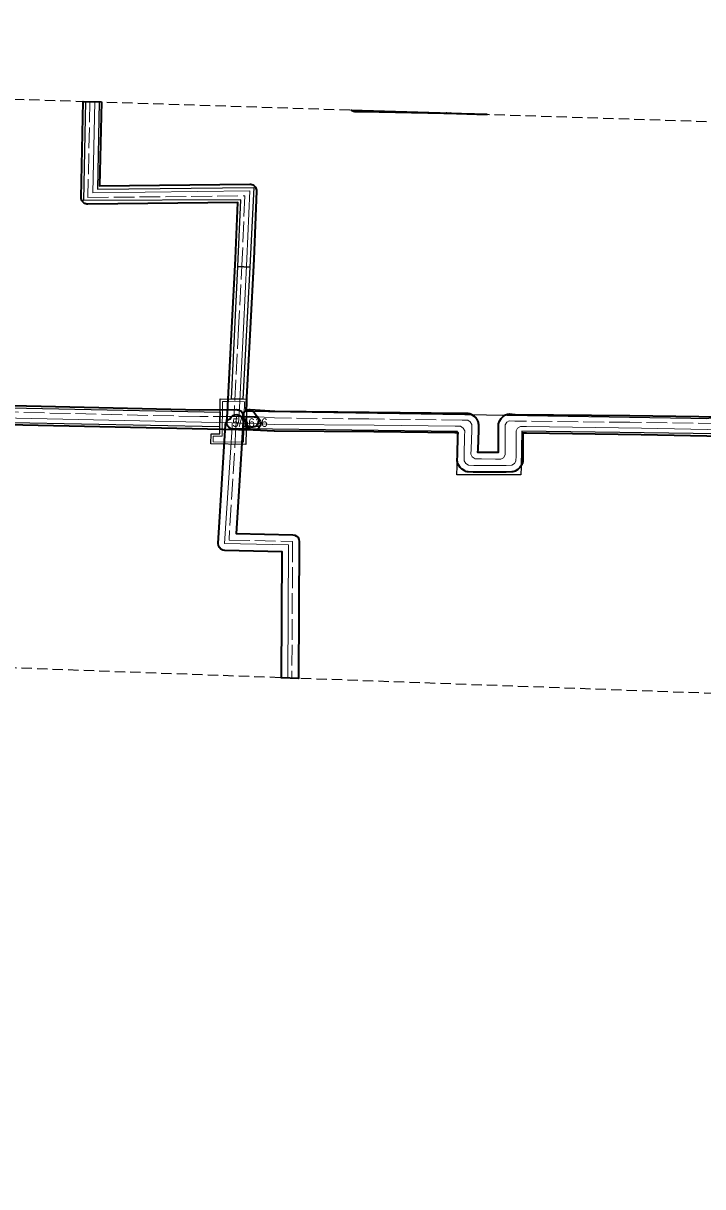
# Model space of a CAD drawing. Extents: x -451331 to -449998, y -1101254 to -1101132.
# Drawn here: x -451083.4 to -451012.5, y -1101253.5 to -1101132.1 of the extents above; entities that cross this region are included whole.
import ezdxf

# ---------------------------------------------------------------- set-up
doc = ezdxf.new("R2010")
doc.units = 0
doc.header["$LTSCALE"] = 0.36
doc.linetypes.add('LONG_DASHED', pattern=[7.5, 6, -1.5])
doc.linetypes.add('MEDIUM_DASHED', pattern=[4.5, 3, -1.5])
for name, color, linetype, lineweight in [('2', 7, 'Continuous', 13), ('3', 7, 'Continuous', 25), ('62', 7, 'MEDIUM_DASHED', 25), ('8', 7, 'Continuous', 35)]:
    doc.layers.add(name, color=color, linetype=linetype, lineweight=lineweight)

msp = doc.modelspace()

# ---------------------------------------------------------------- linework, layer by layer
at = {"layer": '2'}
for q in [(-451061.646, -1101174.239), (-451060.96, -1101173.819)]:
    msp.add_line((-451061.616, -1101173.805), q, dxfattribs=at)
at = {"layer": '2', "linetype": 'LONG_DASHED'}
for p, q in [((-451061.43, -1101172.861), (-451061.444, -1101173.121)), ((-451061.169, -1101173.119), (-451061.444, -1101173.121)), ((-451061.169, -1101173.119), (-451061.235, -1101174.261))]:
    msp.add_line(p, q, dxfattribs=at)
for points in [[(-451076.479, -1101140.271), (-451076.692, -1101150.286), (-451060.305, -1101150.097), (-451060.581, -1101156.665), (-451060.955, -1101163.903), (-451061.43, -1101172.861)], [(-451061.444, -1101173.121), (-451065.019, -1101173.141), (-451093.694, -1101172.465), (-451093.775, -1101176.839), (-451096.67, -1101176.755), (-451096.583, -1101172.448), (-451134.264, -1101171.549)], [(-451008.119, -1101173.899), (-451020.119, -1101173.739), (-451032.119, -1101173.609), (-451032.722, -1101173.571), (-451032.966, -1101173.719), (-451033.129, -1101173.986), (-451033.119, -1101174.579), (-451033.14, -1101176.469), (-451033.13, -1101177.147), (-451033.314, -1101177.432), (-451033.583, -1101177.57), (-451034.159, -1101177.57), (-451035.619, -1101177.55), (-451036.27, -1101177.539), (-451036.57, -1101177.359), (-451036.719, -1101177.075), (-451036.7, -1101176.559), (-451036.63, -1101174.55), (-451036.63, -1101173.975), (-451036.773, -1101173.677), (-451037.039, -1101173.5), (-451037.63, -1101173.5), (-451047.35, -1101173.39), (-451057.196, -1101173.282), (-451059.8, -1101173.111), (-451060.769, -1101173.117), (-451061.169, -1101173.119)], [(-451061.235, -1101174.261), (-451061.953, -1101186.032), (-451055.321, -1101186.173), (-451055.396, -1101200.438)]]:
    msp.add_lwpolyline(points, dxfattribs=at)
at = {"layer": '2'}
for points in [[(-451060.911, -1101172.876), (-451060.456, -1101163.929), (-451060.081, -1101156.689), (-451059.784, -1101149.591), (-451076.181, -1101149.78), (-451075.979, -1101140.287)], [(-451134.59, -1101172.149), (-451115.837, -1101172.598), (-451097.604, -1101173.075), (-451097.719, -1101177.554), (-451092.388, -1101177.693), (-451092.213, -1101173.145), (-451061.616, -1101173.805)], [(-451060.96, -1101173.819), (-451060.934, -1101173.324), (-451060.911, -1101172.876)], [(-451060.96, -1101173.819), (-451060.643, -1101173.826), (-451059.364, -1101173.853), (-451057.211, -1101173.974), (-451046.82, -1101174.05), (-451038.369, -1101174.149), (-451037.795, -1101174.159), (-451037.527, -1101174.344), (-451037.35, -1101174.635), (-451037.369, -1101175.179), (-451037.42, -1101177.16), (-451037.429, -1101177.777), (-451037.246, -1101178.042), (-451036.968, -1101178.21), (-451036.42, -1101178.239), (-451033.03, -1101178.23), (-451032.453, -1101178.22), (-451032.177, -1101178.055), (-451032.005, -1101177.807), (-451031.979, -1101177.239), (-451031.979, -1101175.179), (-451031.999, -1101174.642), (-451031.836, -1101174.341), (-451031.529, -1101174.184), (-451030.92, -1101174.179), (-451018.92, -1101174.35), (-451006.92, -1101174.589)], [(-451061.646, -1101174.239), (-451062.416, -1101186.398), (-451055.75, -1101186.532), (-451055.805, -1101200.423)]]:
    msp.add_lwpolyline(points, dxfattribs=at)
at = {"layer": '3'}
for points in [[(-451059.796, -1101157.55), (-451061.045, -1101157.47), (-451060.711, -1101150.513), (-451077.11, -1101150.608), (-451076.885, -1101140.258), (-451075.502, -1101140.303), (-451075.696, -1101149.419), (-451059.368, -1101149.249)], [(-451059.796, -1101157.55), (-451060.508, -1101171.324), (-451061.708, -1101171.306), (-451061.045, -1101157.47)], [(-451233.493, -1101184.878), (-451233.467, -1101183.091), (-451218.452, -1101183.247), (-451218.207, -1101169.503), (-451211.129, -1101169.683), (-451179.854, -1101170.248), (-451124.903, -1101171.322), (-451098.285, -1101171.957), (-451062.886, -1101172.679), (-451062.939, -1101174.227), (-451091.782, -1101173.66), (-451091.956, -1101178.155), (-451098.179, -1101177.951), (-451098.066, -1101173.513), (-451151.771, -1101172.189), (-451216.533, -1101171.189), (-451216.652, -1101185.03)], [(-451063.84, -1101175.989), (-451063.82, -1101174.929), (-451062.925, -1101174.939), (-451062.878, -1101171.289), (-451060.086, -1101171.331), (-451060.189, -1101176.052)], [(-451031.478, -1101178.392), (-451031.501, -1101179.236), (-451038.169, -1101179.216), (-451038.153, -1101178.327), (-451038.111, -1101174.703), (-451060.154, -1101174.434), (-451060.114, -1101172.594), (-451035.097, -1101172.968), (-451013.743, -1101173.315), (-451012.161, -1101173.348), (-451009.999, -1101173.067), (-450992.816, -1101173.411), (-450992.865, -1101173.754), (-450992.823, -1101173.755), (-450992.851, -1101175.262), (-451002.429, -1101175.114), (-451013.496, -1101174.908), (-451031.383, -1101174.657)]]:
    msp.add_lwpolyline(points, close=True, dxfattribs=at)
at = {"layer": '3', "lineweight": 13}
msp.add_lwpolyline([(-451062.002, -1101171.569), (-451060.332, -1101171.59), (-451060.449, -1101175.809), (-451063.621, -1101175.767), (-451063.601, -1101175.198), (-451062.682, -1101175.185), (-451062.644, -1101171.561)], close=True, dxfattribs=at)
at = {"layer": '62'}
msp.add_lwpolyline([(-450786.261, -1101210.25), (-451322.174, -1101190.711), (-451330.547, -1101132.096), (-450766.722, -1101150.239), (-450459.689, -1101190.711), (-449997.743, -1101194.898), (-449997.743, -1101249.327), (-450456.897, -1101253.514)], close=True, dxfattribs=at)
at = {"layer": '8'}
for points in [[(-451075.28, -1101140.31), (-451075.465, -1101149.072), (-451059.792, -1101148.891), (-451059.678, -1101148.899), (-451059.568, -1101148.925), (-451059.463, -1101148.969), (-451059.367, -1101149.029), (-451059.281, -1101149.104), (-451059.209, -1101149.191), (-451059.152, -1101149.289), (-451059.111, -1101149.396), (-451059.089, -1101149.507), (-451059.084, -1101149.62), (-451059.382, -1101156.718), (-451059.382, -1101156.725), (-451059.757, -1101163.965), (-451060.197, -1101172.46), (-451059.906, -1101172.455), (-451059.796, -1101172.461), (-451059.688, -1101172.485), (-451059.586, -1101172.525), (-451059.491, -1101172.58), (-451059.406, -1101172.65), (-451059.333, -1101172.733), (-451059.023, -1101173.142), (-451058.96, -1101173.243), (-451058.915, -1101173.353), (-451058.889, -1101173.469), (-451058.883, -1101173.587), (-451058.898, -1101173.705), (-451058.931, -1101173.819), (-451058.984, -1101173.926), (-451059.054, -1101174.022), (-451059.139, -1101174.105), (-451059.237, -1101174.172), (-451059.345, -1101174.221), (-451059.46, -1101174.252), (-451059.578, -1101174.263), (-451059.696, -1101174.254), (-451059.812, -1101174.225), (-451059.92, -1101174.177), (-451060.026, -1101174.275), (-451060.109, -1101174.341), (-451060.201, -1101174.393), (-451060.3, -1101174.432), (-451060.403, -1101174.454), (-451060.509, -1101174.461), (-451061.506, -1101174.452), (-451061.62, -1101174.442), (-451061.732, -1101174.412), (-451061.837, -1101174.365), (-451061.933, -1101174.302), (-451062.017, -1101174.223), (-451062.087, -1101174.132), (-451062.142, -1101174.03), (-451062.179, -1101173.921), (-451062.197, -1101173.808), (-451062.197, -1101173.693), (-451062.111, -1101172.683), (-451061.654, -1101163.867), (-451061.28, -1101156.633), (-451061.036, -1101150.806), (-451076.683, -1101150.986), (-451076.795, -1101150.978), (-451076.905, -1101150.953), (-451077.008, -1101150.91), (-451077.104, -1101150.852), (-451077.189, -1101150.779), (-451077.261, -1101150.693), (-451077.319, -1101150.597), (-451077.36, -1101150.493), (-451077.385, -1101150.383), (-451077.391, -1101150.271), (-451077.179, -1101140.249)], [(-451038.96, -1101141.525), (-451039.005, -1101141.526), (-451039.019, -1101141.526), (-451039.508, -1101141.517), (-451039.54, -1101141.516), (-451047.949, -1101141.35), (-451047.963, -1101141.35), (-451047.965, -1101141.35), (-451048.745, -1101141.334), (-451048.777, -1101141.333), (-451048.823, -1101141.329), (-451048.868, -1101141.321), (-451048.913, -1101141.311), (-451048.957, -1101141.297), (-451048.999, -1101141.281), (-451049.041, -1101141.262), (-451049.082, -1101141.241), (-451049.12, -1101141.217), (-451049.158, -1101141.19), (-451049.193, -1101141.161), (-451049.206, -1101141.149), (-451038.768, -1101141.485), (-451038.781, -1101141.489), (-451038.824, -1101141.503), (-451038.869, -1101141.513), (-451038.914, -1101141.521)], [(-451035.021, -1101141.605), (-451039.022, -1101141.526), (-451039.14, -1101141.514), (-451039.254, -1101141.481), (-451039.281, -1101141.468)], [(-451061.847, -1101173.373), (-451061.737, -1101173.186), (-451061.573, -1101173.041), (-451061.372, -1101172.954), (-451061.154, -1101172.933), (-451060.94, -1101172.98), (-451060.751, -1101173.091), (-451060.606, -1101173.255), (-451060.519, -1101173.456), (-451060.498, -1101173.674), (-451061.21, -1101185.347), (-451055.306, -1101185.474), (-451055.093, -1101185.512), (-451054.902, -1101185.613), (-451054.75, -1101185.769), (-451054.654, -1101185.963), (-451054.622, -1101186.177), (-451054.696, -1101200.463), (-451056.495, -1101200.398), (-451056.427, -1101187.251), (-451062.391, -1101187.123), (-451062.612, -1101187.083), (-451062.809, -1101186.974), (-451062.961, -1101186.809), (-451063.053, -1101186.604), (-451063.075, -1101186.381), (-451062.321, -1101173.987), (-451062.274, -1101173.773), (-451062.163, -1101173.584), (-451061.999, -1101173.439)]]:
    msp.add_lwpolyline(points, close=True, dxfattribs=at)
for points in [[(-451093.678, -1101171.765), (-451065.013, -1101172.441), (-451061.173, -1101172.419), (-451061.062, -1101172.427), (-451060.954, -1101172.453), (-451060.851, -1101172.496), (-451060.756, -1101172.554), (-451060.672, -1101172.627), (-451060.6, -1101172.712), (-451060.543, -1101172.807), (-451060.501, -1101172.91), (-451060.476, -1101173.019), (-451060.469, -1101173.129), (-451059.348, -1101173.154), (-451059.228, -1101173.168), (-451059.112, -1101173.203), (-451059.004, -1101173.257), (-451058.906, -1101173.33), (-451058.823, -1101173.418), (-451058.756, -1101173.519), (-451058.707, -1101173.63), (-451058.679, -1101173.747), (-451058.671, -1101173.868), (-451058.684, -1101173.989), (-451058.718, -1101174.105), (-451058.771, -1101174.214), (-451058.842, -1101174.312), (-451058.929, -1101174.397), (-451059.03, -1101174.465), (-451059.14, -1101174.514), (-451059.258, -1101174.544), (-451059.379, -1101174.553), (-451091.54, -1101173.86)], [(-451057.25, -1101174.673), (-451059.403, -1101174.552), (-451059.517, -1101174.537), (-451059.627, -1101174.503), (-451059.73, -1101174.451), (-451059.824, -1101174.383), (-451059.905, -1101174.301), (-451059.971, -1101174.206), (-451060.021, -1101174.102), (-451060.053, -1101173.991), (-451060.066, -1101173.877), (-451060.061, -1101173.761), (-451060.165, -1101173.71), (-451060.259, -1101173.641), (-451060.34, -1101173.558), (-451060.406, -1101173.462), (-451060.456, -1101173.357), (-451060.488, -1101173.246), (-451060.501, -1101173.13), (-451060.494, -1101173.014), (-451060.468, -1101172.901), (-451060.424, -1101172.793), (-451060.363, -1101172.694), (-451060.286, -1101172.607), (-451060.196, -1101172.534), (-451060.095, -1101172.476), (-451059.985, -1101172.436), (-451059.871, -1101172.415), (-451059.755, -1101172.413), (-451057.17, -1101172.583), (-451047.342, -1101172.69), (-451037.626, -1101172.8), (-451037.039, -1101172.8), (-451036.937, -1101172.807), (-451036.837, -1101172.829), (-451036.741, -1101172.866), (-451036.651, -1101172.917), (-451036.385, -1101173.094), (-451036.311, -1101173.151), (-451036.246, -1101173.217), (-451036.189, -1101173.291), (-451036.143, -1101173.372), (-451035.999, -1101173.671), (-451035.961, -1101173.768), (-451035.937, -1101173.87), (-451035.929, -1101173.975), (-451035.929, -1101174.55), (-451035.93, -1101174.574), (-451036, -1101176.585), (-451036.01, -1101176.843), (-451035.609, -1101176.85), (-451034.155, -1101176.87), (-451033.834, -1101176.87), (-451033.839, -1101176.48), (-451033.84, -1101176.462), (-451033.82, -1101174.582), (-451033.829, -1101173.998), (-451033.824, -1101173.899), (-451033.805, -1101173.802), (-451033.772, -1101173.708), (-451033.726, -1101173.621), (-451033.563, -1101173.354), (-451033.498, -1101173.264), (-451033.42, -1101173.186), (-451033.33, -1101173.122), (-451033.086, -1101172.973), (-451032.99, -1101172.924), (-451032.889, -1101172.891), (-451032.784, -1101172.873), (-451032.677, -1101172.872), (-451032.093, -1101172.91), (-451020.111, -1101173.04), (-451008.108, -1101173.2)], [(-451006.933, -1101175.289), (-451018.931, -1101175.049), (-451030.922, -1101174.879), (-451031.29, -1101174.882), (-451031.28, -1101175.154), (-451031.28, -1101175.179), (-451031.28, -1101177.239), (-451031.28, -1101177.271), (-451031.306, -1101177.839), (-451031.317, -1101177.936), (-451031.342, -1101178.031), (-451031.379, -1101178.121), (-451031.429, -1101178.206), (-451031.601, -1101178.454), (-451031.664, -1101178.532), (-451031.737, -1101178.6), (-451031.819, -1101178.657), (-451032.095, -1101178.821), (-451032.204, -1101178.874), (-451032.321, -1101178.907), (-451032.441, -1101178.92), (-451033.017, -1101178.929), (-451033.027, -1101178.929), (-451036.417, -1101178.94), (-451036.438, -1101178.939), (-451036.458, -1101178.938), (-451037.006, -1101178.909), (-451037.118, -1101178.893), (-451037.227, -1101178.86), (-451037.329, -1101178.809), (-451037.607, -1101178.641), (-451037.688, -1101178.585), (-451037.759, -1101178.518), (-451037.821, -1101178.441), (-451038.004, -1101178.177), (-451038.059, -1101178.083), (-451038.099, -1101177.981), (-451038.123, -1101177.875), (-451038.129, -1101177.766), (-451038.119, -1101177.148), (-451038.119, -1101177.142), (-451038.069, -1101175.162), (-451038.069, -1101175.154), (-451038.058, -1101174.855), (-451038.38, -1101174.849), (-451046.826, -1101174.75), (-451057.216, -1101174.674), (-451057.23, -1101174.674)]]:
    msp.add_lwpolyline(points, dxfattribs=at)

# ---------------------------------------------------------------- texts
at = {"layer": '3'}
msp.add_text('5/1616 ', height=0.9, dxfattribs=at).set_placement((-451061.614, -1101174.219))

doc.saveas('drawing.dxf')
